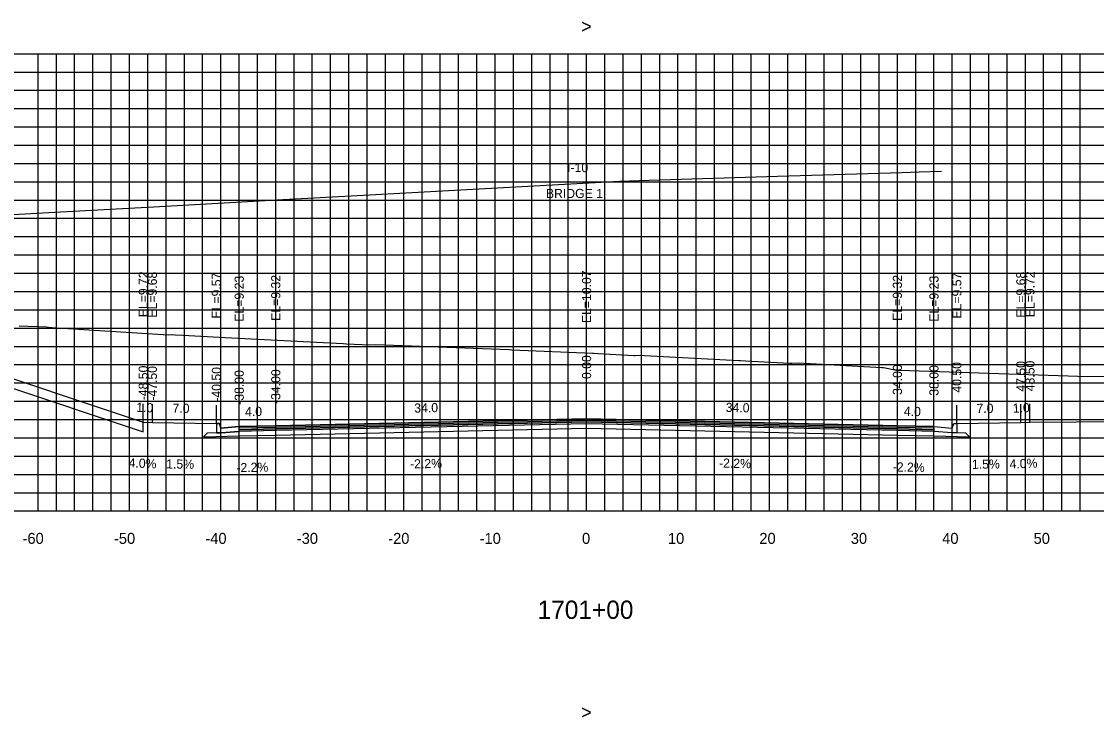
# Model space of a CAD drawing. Extents: x 1797789 to 1803805, y 249066 to 250293.
# Drawn here: x 1802229.2 to 1802346.8, y 250176.8 to 250253 of the extents above; entities that cross this region are included whole.
import ezdxf

# ---------------------------------------------------------------- set-up
doc = ezdxf.new("R2010")
doc.units = 0
for name, color, linetype in [('1', 7, 'Continuous'), ('10', 7, 'Continuous'), ('3', 7, 'Continuous'), ('4', 7, 'Continuous'), ('60', 7, 'Continuous'), ('BASE', 7, 'Continuous'), ('CL-CNST', 7, 'Continuous'), ('Level 62', 7, 'Continuous'), ('LOWER BINDER', 7, 'Continuous'), ('M-ROADS', 7, 'Continuous'), ('UPPER BINDER', 7, 'Continuous'), ('WEARING', 7, 'Continuous')]:
    doc.layers.add(name, color=color, linetype=linetype)

msp = doc.modelspace()

# ---------------------------------------------------------------- linework, layer by layer
for p, q in [((1802242.5, 250209.15), (1802242.5, 250211.15)), ((1802243.5, 250209.11), (1802243.5, 250211.11)), ((1802250.5, 250209), (1802250.5, 250211)), ((1802250.5, 250209), (1802250.5, 250211)), ((1802253, 250208.66), (1802253, 250210.66)), ((1802257, 250208.75), (1802257, 250210.75)), ((1802291, 250209.5), (1802291, 250211.5)), ((1802325, 250208.75), (1802325, 250210.75)), ((1802329, 250208.66), (1802329, 250210.66)), ((1802331.5, 250209), (1802331.5, 250211)), ((1802331.5, 250209), (1802331.5, 250211)), ((1802338.5, 250209.11), (1802338.5, 250211.11)), ((1802339.5, 250209.15), (1802339.5, 250211.15))]:
    msp.add_line(p, q)
for points in [[(1802253, 250208.66), (1802251, 250208.5), (1802250.83, 250209), (1802250.5, 250209), (1802250.5, 250207.97), (1802251, 250207.97), (1802253, 250208.13)], [(1802329, 250208.66), (1802331, 250208.5), (1802331.17, 250209), (1802331.5, 250209), (1802331.5, 250207.97), (1802331, 250207.97), (1802329, 250208.13)]]:
    msp.add_lwpolyline(points, close=True)
at = {"layer": '60'}
for p, q in [((1802141, 250199.43), (1802441, 250199.43)), ((1802231, 250199.37), (1802231, 250199.43)), ((1802241, 250199.37), (1802241, 250199.43)), ((1802251, 250199.37), (1802251, 250199.43)), ((1802261, 250199.37), (1802261, 250199.43)), ((1802271, 250199.37), (1802271, 250199.43)), ((1802281, 250199.37), (1802281, 250199.43)), ((1802291, 250199.37), (1802291, 250199.43)), ((1802301, 250199.37), (1802301, 250199.43)), ((1802311, 250199.37), (1802311, 250199.43)), ((1802321, 250199.37), (1802321, 250199.43)), ((1802331, 250199.37), (1802331, 250199.43)), ((1802341, 250199.37), (1802341, 250199.43))]:
    msp.add_line(p, q, dxfattribs=at)
at = {"layer": 'BASE'}
msp.add_lwpolyline([(1802329, 250207.63), (1802332.9, 250207.55), (1802332.5, 250207.95), (1802331.5, 250207.97), (1802331, 250207.97), (1802329, 250208.13), (1802325, 250208.22), (1802291, 250208.97), (1802257, 250208.22), (1802253, 250208.13), (1802251, 250207.97), (1802250.5, 250207.97), (1802249.5, 250207.95), (1802249.1, 250207.55), (1802253, 250207.63), (1802257, 250207.72), (1802291, 250208.47), (1802325, 250207.72)], close=True, dxfattribs=at)
at = {"layer": 'CL-CNST'}
for p, q in [((1802179.36, 250229.14), (1802242.5, 250208.09)), ((1802242.5, 250208.09), (1802242.5, 250209.15))]:
    msp.add_line(p, q, dxfattribs=at)
for points in [[(1802218.42, 250231.31), (1802233.5, 250232.14), (1802243.61, 250232.7), (1802249.44, 250233.02), (1802257.76, 250233.48), (1802265.23, 250233.89), (1802270.58, 250234.18), (1802294.61, 250235.5), (1802297.86, 250235.6), (1802311.88, 250236.03), (1802325.47, 250236.44), (1802327.39, 250236.5), (1802329.83, 250236.57)], [(1802182.07, 250229.29), (1802242.5, 250209.15), (1802243.5, 250209.11), (1802250.5, 250209), (1802250.5, 250209), (1802250.83, 250209), (1802251, 250208.5), (1802253, 250208.66), (1802257, 250208.75), (1802291, 250209.5), (1802325, 250208.75), (1802329, 250208.66), (1802331, 250208.5), (1802331.17, 250209), (1802331.5, 250209), (1802331.5, 250209), (1802338.5, 250209.11), (1802339.5, 250209.15), (1802441, 250209.87)]]:
    msp.add_lwpolyline(points, dxfattribs=at)
at = {"layer": 'Level 62'}
for p, q in [((1802141, 250249.43), (1802441, 250249.43)), ((1802231, 250199.43), (1802231, 250249.43)), ((1802233, 250199.43), (1802233, 250249.43)), ((1802235, 250199.43), (1802235, 250249.43)), ((1802237, 250199.43), (1802237, 250249.43)), ((1802239, 250199.43), (1802239, 250249.43)), ((1802241, 250199.43), (1802241, 250249.43)), ((1802243, 250199.43), (1802243, 250249.43)), ((1802245, 250199.43), (1802245, 250249.43)), ((1802247, 250199.43), (1802247, 250249.43)), ((1802249, 250199.43), (1802249, 250249.43)), ((1802251, 250199.43), (1802251, 250249.43)), ((1802253, 250199.43), (1802253, 250249.43)), ((1802255, 250199.43), (1802255, 250249.43)), ((1802257, 250199.43), (1802257, 250249.43)), ((1802259, 250199.43), (1802259, 250249.43)), ((1802261, 250199.43), (1802261, 250249.43)), ((1802263, 250199.43), (1802263, 250249.43)), ((1802265, 250199.43), (1802265, 250249.43)), ((1802267, 250199.43), (1802267, 250249.43)), ((1802269, 250199.43), (1802269, 250249.43)), ((1802271, 250199.43), (1802271, 250249.43)), ((1802273, 250199.43), (1802273, 250249.43)), ((1802275, 250199.43), (1802275, 250249.43)), ((1802277, 250199.43), (1802277, 250249.43)), ((1802279, 250199.43), (1802279, 250249.43)), ((1802281, 250199.43), (1802281, 250249.43)), ((1802283, 250199.43), (1802283, 250249.43)), ((1802285, 250199.43), (1802285, 250249.43)), ((1802287, 250199.43), (1802287, 250249.43)), ((1802289, 250199.43), (1802289, 250249.43)), ((1802291, 250199.43), (1802291, 250249.43)), ((1802293, 250199.43), (1802293, 250249.43)), ((1802295, 250199.43), (1802295, 250249.43)), ((1802297, 250199.43), (1802297, 250249.43)), ((1802299, 250199.43), (1802299, 250249.43)), ((1802301, 250199.43), (1802301, 250249.43)), ((1802303, 250199.43), (1802303, 250249.43)), ((1802305, 250199.43), (1802305, 250249.43)), ((1802307, 250199.43), (1802307, 250249.43)), ((1802309, 250199.43), (1802309, 250249.43)), ((1802311, 250199.43), (1802311, 250249.43)), ((1802313, 250199.43), (1802313, 250249.43)), ((1802315, 250199.43), (1802315, 250249.43)), ((1802317, 250199.43), (1802317, 250249.43)), ((1802319, 250199.43), (1802319, 250249.43)), ((1802321, 250199.43), (1802321, 250249.43)), ((1802323, 250199.43), (1802323, 250249.43)), ((1802325, 250199.43), (1802325, 250249.43)), ((1802327, 250199.43), (1802327, 250249.43)), ((1802329, 250199.43), (1802329, 250249.43)), ((1802331, 250199.43), (1802331, 250249.43)), ((1802333, 250199.43), (1802333, 250249.43)), ((1802335, 250199.43), (1802335, 250249.43)), ((1802337, 250199.43), (1802337, 250249.43)), ((1802339, 250199.43), (1802339, 250249.43)), ((1802341, 250199.43), (1802341, 250249.43)), ((1802343, 250199.43), (1802343, 250249.43)), ((1802345, 250199.43), (1802345, 250249.43)), ((1802141, 250247.43), (1802441, 250247.43)), ((1802141, 250245.43), (1802441, 250245.43)), ((1802141, 250243.43), (1802441, 250243.43)), ((1802141, 250241.43), (1802441, 250241.43)), ((1802141, 250239.43), (1802441, 250239.43)), ((1802141, 250237.43), (1802441, 250237.43)), ((1802141, 250235.43), (1802441, 250235.43)), ((1802141, 250233.43), (1802441, 250233.43)), ((1802141, 250231.43), (1802441, 250231.43)), ((1802141, 250229.43), (1802441, 250229.43)), ((1802141, 250227.43), (1802441, 250227.43)), ((1802141, 250225.43), (1802441, 250225.43)), ((1802141, 250223.43), (1802441, 250223.43)), ((1802141, 250221.43), (1802441, 250221.43)), ((1802141, 250219.43), (1802441, 250219.43)), ((1802141, 250217.43), (1802441, 250217.43)), ((1802141, 250215.43), (1802441, 250215.43)), ((1802141, 250213.43), (1802441, 250213.43)), ((1802141, 250211.43), (1802441, 250211.43)), ((1802141, 250209.43), (1802441, 250209.43)), ((1802141, 250207.43), (1802441, 250207.43)), ((1802141, 250205.43), (1802441, 250205.43)), ((1802141, 250203.43), (1802441, 250203.43)), ((1802141, 250201.43), (1802441, 250201.43)), ((1802141, 250199.43), (1802441, 250199.43))]:
    msp.add_line(p, q, dxfattribs=at)
at = {"layer": 'LOWER BINDER'}
msp.add_lwpolyline([(1802253, 250208.13), (1802253, 250208.32), (1802257, 250208.41), (1802291, 250209.16), (1802325, 250208.41), (1802329, 250208.32), (1802329, 250208.13), (1802325, 250208.22), (1802291, 250208.97), (1802257, 250208.22)], close=True, dxfattribs=at)
at = {"layer": 'M-ROADS'}
msp.add_lwpolyline([(1802228.92, 250219.69), (1802231.91, 250219.55), (1802232.4, 250219.51), (1802232.52, 250219.5), (1802245.28, 250218.68), (1802245.63, 250218.72), (1802245.65, 250218.73), (1802245.98, 250218.69), (1802246.82, 250218.65), (1802251.45, 250218.4), (1802262.18, 250217.87), (1802264.36, 250217.76), (1802264.69, 250217.72), (1802264.74, 250217.72), (1802267.3, 250217.61), (1802267.96, 250217.64), (1802282.54, 250217.08), (1802282.82, 250217.05), (1802291.68, 250216.69), (1802291.81, 250216.68), (1802292.28, 250216.64), (1802296.17, 250216.42), (1802296.33, 250216.44), (1802296.63, 250216.47), (1802307.65, 250215.89), (1802307.82, 250215.88), (1802308.39, 250215.84), (1802313.25, 250215.59), (1802313.47, 250215.6), (1802314.13, 250215.62), (1802323.29, 250215.12), (1802323.49, 250215.1), (1802324.91, 250214.83), (1802325.02, 250214.82), (1802325.25, 250214.83), (1802345.82, 250214.15), (1802350.23, 250214.19)], dxfattribs=at)
at = {"layer": 'UPPER BINDER'}
msp.add_lwpolyline([(1802291, 250209.16), (1802257, 250208.41), (1802253, 250208.32), (1802253, 250208.51), (1802257, 250208.6), (1802291, 250209.35), (1802325, 250208.6), (1802329, 250208.51), (1802329, 250208.13), (1802329, 250208.32), (1802325, 250208.41)], close=True, dxfattribs=at)
at = {"layer": 'WEARING'}
msp.add_lwpolyline([(1802329, 250208.51), (1802329, 250208.66), (1802325, 250208.75), (1802291, 250209.5), (1802257, 250208.75), (1802253, 250208.66), (1802253, 250208.51), (1802257, 250208.6), (1802291, 250209.35), (1802325, 250208.6)], close=True, dxfattribs=at)

# ---------------------------------------------------------------- texts
at = {"layer": '1'}
msp.add_text('1701+00', height=2, dxfattribs=at).set_placement((1802285.64, 250187.63))
at = {"layer": '10'}
for s, p in [('-60', (1802229.3, 250195.83)), ('-50', (1802239.3, 250195.83)), ('-40', (1802249.3, 250195.83)), ('-30', (1802259.3, 250195.83)), ('-20', (1802269.3, 250195.83)), ('-10', (1802279.3, 250195.83)), ('0', (1802290.5, 250195.83)), ('10', (1802299.9, 250195.83)), ('20', (1802309.9, 250195.83)), ('30', (1802319.9, 250195.83)), ('40', (1802329.9, 250195.83)), ('50', (1802339.9, 250195.83))]:
    msp.add_text(s, height=1.2, dxfattribs=at).set_placement(p)
at = {"layer": '3'}
for s, p in [('I-10 ', (1802288.87, 250236.48)), ('BRIDGE 1', (1802286.55, 250233.65))]:
    msp.add_text(s, height=1, dxfattribs=at).set_placement(p)
for s, p in [('EL=9.72', (1802243, 250220.61)), ('EL=9.68', (1802244, 250220.57)), ('EL=9.57', (1802251, 250220.47)), ('EL=9.57', (1802251, 250220.47)), ('EL=9.23', (1802253.5, 250220.13)), ('EL=9.32', (1802257.5, 250220.22)), ('EL=10.07', (1802291.5, 250219.97)), ('EL=9.32', (1802325.5, 250220.22)), ('EL=9.23', (1802329.5, 250220.13)), ('EL=9.57', (1802332, 250220.47)), ('EL=9.57', (1802332, 250220.47)), ('EL=9.68', (1802339, 250220.57)), ('EL=9.72', (1802340, 250220.61)), ('0.00', (1802291.5, 250213.86)), ('-48.50', (1802243, 250211.53)), ('-47.50', (1802244, 250211.49)), ('-40.50', (1802251, 250211.38)), ('-40.50', (1802251, 250211.38)), ('34.00', (1802325.5, 250212.12)), ('38.00', (1802329.5, 250212.03)), ('40.50', (1802332, 250212.37)), ('40.50', (1802332, 250212.37)), ('47.50', (1802339, 250212.48)), ('48.50', (1802340, 250212.52)), ('-38.00', (1802253.5, 250211.04)), ('-34.00', (1802257.5, 250211.13))]:
    msp.add_text(s, height=1, rotation=90, dxfattribs=at).set_placement(p)
at = {"layer": '4'}
for s, rotation, p in [('1.0', 357.7094, (1802241.72, 250210.28)), ('7.0', 359.1406, (1802245.7, 250210.18)), ('4.0', 1.2603, (1802253.65, 250209.78)), ('34.0', 1.2603, (1802272.16, 250210.18)), ('34.0', 358.7397, (1802306.21, 250210.26)), ('4.0', 358.7397, (1802325.7, 250209.84)), ('7.0', 0.8594, (1802333.66, 250210.14)), ('1.0', 2.2906, (1802337.64, 250210.17)), ('4.0%', 357.7094, (1802240.89, 250204.21)), ('1.5%', 359.1406, (1802245.01, 250204.08)), ('-2.2%', 1.2603, (1802252.7, 250203.66)), ('-2.2%', 1.2603, (1802271.7, 250204.07)), ('-2.2%', 358.7397, (1802305.48, 250204.18)), ('-2.2%', 358.7397, (1802324.48, 250203.76)), ('1.5%', 0.8594, (1802333.16, 250204.03)), ('4.0%', 2.2906, (1802337.29, 250204.06))]:
    msp.add_text(s, height=1, rotation=rotation, dxfattribs=at).set_placement(p)
at = {"layer": '60'}
for p in [(1802290.39, 250251.68), (1802290.39, 250176.68)]:
    msp.add_text('>', height=1.5, dxfattribs=at).set_placement(p)

doc.saveas('drawing.dxf')
